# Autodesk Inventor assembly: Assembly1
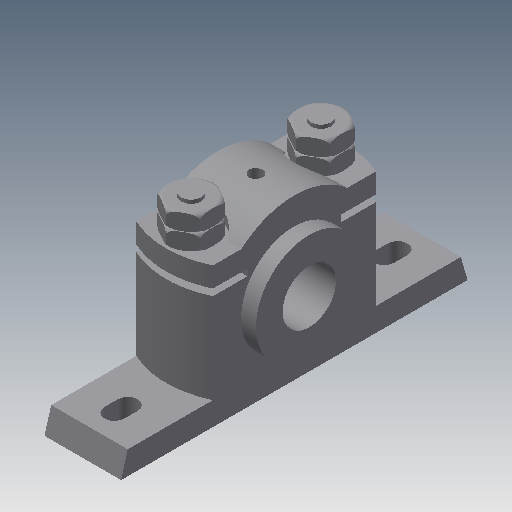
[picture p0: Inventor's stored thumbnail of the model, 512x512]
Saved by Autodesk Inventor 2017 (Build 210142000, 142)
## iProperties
Created: 2016-03
Part Number: Assembly1
Document SubType Name: Assembly
Designer: Sandeep
Author: Sandeep
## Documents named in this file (7)
- C:\Inventor_2017\c13\Plumber block\Assembly1.iam
- C:\Inventor_2017\c13\Plumber block\Casting.ipt
- C:\Inventor_2017\c13\Plumber block\Brasses.ipt
- C:\Inventor_2017\c13\Plumber block\Cap.ipt
- C:\Inventor_2017\c13\Plumber block\Bolt.ipt
- C:\Inventor_2017\c13\Plumber block\Nut.ipt
- C:\Inventor_2017\c13\Plumber block\Lock Nut.ipt
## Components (9 placed, 6 different names)
1. Casting:1 — Mate:1, Mate:2, Insert:1, Insert:2, Angle:1, Angle:2
2. Brasses:1 — Mate:1, Mate:2, Mate:3, Mate:4
3. Cap:1 — Mate:3, Mate:4, Insert:3, Insert:5
4. Bolt:1 — Insert:1, Angle:1
5. Bolt:2 — Insert:2, Angle:2
6. Nut:1 — Insert:3, Insert:4
7. Nut:2 — Insert:5, Insert:6
8. Lock Nut:1 — Insert:4
9. Lock Nut:2 — Insert:6
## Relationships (12: Insert 6, Mate 4, Angle 2)
- Mate:1: Casting:1 ↔ Brasses:1
- Mate:2: Casting:1 ↔ Brasses:1
- Mate:3: Brasses:1 ↔ Cap:1
- Mate:4: Brasses:1 ↔ Cap:1
- Insert:1: Casting:1 ↔ Bolt:1
- Insert:2: Casting:1 ↔ Bolt:2
- Angle:1: Casting:1 ↔ Bolt:1
- Angle:2: Casting:1 ↔ Bolt:2
- Insert:3: Cap:1 ↔ Nut:1
- Insert:4: Nut:1 ↔ Lock Nut:1
- Insert:5: Cap:1 ↔ Nut:2
- Insert:6: Nut:2 ↔ Lock Nut:2
